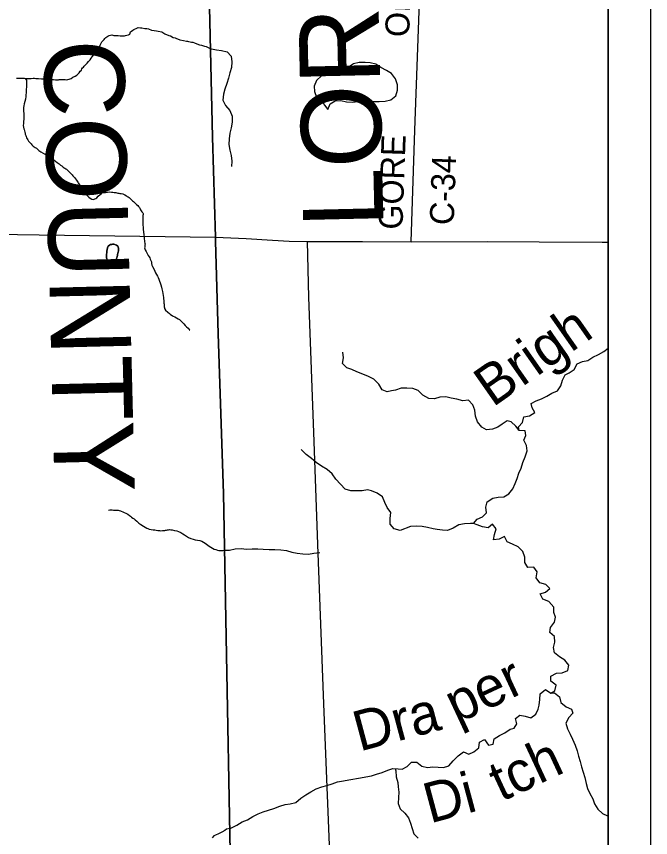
# Model space of a CAD drawing. Extents: x 0 to 34, y 0 to 22.
# Drawn here: x 7.504 to 9, y 15.642 to 17.578 of the extents above; entities that cross this region are included whole.
import ezdxf

# ---------------------------------------------------------------- set-up
doc = ezdxf.new("R2010")
doc.units = 0
for name, color, linetype in [('GM_X_Corporation', 7, 'Continuous'), ('GM_X_County_Road', 7, 'Continuous'), ('GM_X_County_Road_Text', 7, 'Continuous'), ('GM_X_County_Text', 7, 'Continuous'), ('GM_X_Minor_Lake', 7, 'Continuous'), ('GM_X_Minor_River', 7, 'Continuous'), ('GM_X_Minor_River_Text', 7, 'Continuous'), ('GM_X_State_Route', 7, 'Continuous'), ('SH_Data', 7, 'Continuous')]:
    doc.layers.add(name, color=color, linetype=linetype)

msp = doc.modelspace()

# ---------------------------------------------------------------- linework, layer by layer
at = {"layer": 'GM_X_Corporation'}
for points in [[(8.9, 14.1), (8.9, 20.9)], [(8.0153, 15.2273), (7.992, 16.4534), (7.9799, 16.8298), (7.9733, 17.0489), (7.973, 17.0583), (7.9659, 17.2939), (7.9575, 17.6697), (7.951, 17.9078), (7.9387, 18.4008), (7.9196, 19.2769), (6.5603, 19.2769), (6.5603, 19.994)], [(8.0153, 15.2273), (7.992, 16.4534), (7.9799, 16.8298), (7.9733, 17.0489), (7.973, 17.0583), (7.9659, 17.2939), (7.9575, 17.6697), (7.951, 17.9078), (7.9387, 18.4008), (7.9196, 19.2769), (6.5603, 19.2769), (6.5603, 19.994)], [(8.7801, 19.994), (8.7801, 19.2769), (7.9196, 19.2769), (7.9387, 18.4008), (7.951, 17.9078), (7.9575, 17.6697), (7.9659, 17.2939), (7.973, 17.0583), (7.9733, 17.0489), (7.9799, 16.8298), (7.992, 16.4534), (8.0153, 15.2273)]]:
    msp.add_lwpolyline(points, dxfattribs=at)
msp.add_lwpolyline([(7.9196, 19.2769), (7.9387, 18.4008), (7.951, 17.9078), (7.9575, 17.6697), (7.9659, 17.2939), (7.973, 17.0583), (7.9733, 17.0489), (7.9799, 16.8298), (7.992, 16.4534), (8.0153, 15.2273), (8.0262, 14.6555), (8.0297, 14.4963), (8.2922, 14.4944), (8.9, 14.4898), (8.9, 19.6997), (8.7801, 19.7002), (8.7801, 19.2769)], close=True, dxfattribs=at)
at = {"layer": 'GM_X_County_Road'}
for points in [[(8.435, 17.0471), (8.4437, 17.3104), (8.465, 17.8934), (8.4882, 18.5028)], [(8.2463, 15.5263), (8.2291, 15.9577), (8.215, 16.333), (8.206, 16.5759), (8.1937, 16.9162), (8.1904, 17.0478)], [(8.1904, 17.0478), (8.3202, 17.0474), (8.435, 17.0471)]]:
    msp.add_lwpolyline(points, dxfattribs=at)
at = {"layer": 'GM_X_Minor_Lake'}
for points in [[(8.3638, 17.4584), (8.3514, 17.4662), (8.3385, 17.4694), (8.3263, 17.47), (8.3126, 17.4698), (8.2988, 17.467), (8.2873, 17.4592), (8.2736, 17.4556), (8.261, 17.4569), (8.2484, 17.4533), (8.2346, 17.447), (8.2231, 17.4385), (8.2119, 17.4272), (8.2064, 17.4144), (8.2066, 17.4011), (8.2117, 17.3881), (8.2242, 17.3803), (8.2309, 17.3695), (8.2387, 17.3587)], [(8.2387, 17.3587), (8.2439, 17.3727), (8.2561, 17.3798), (8.2687, 17.38), (8.2824, 17.3771), (8.2961, 17.3765), (8.3098, 17.3778), (8.3235, 17.3795), (8.3372, 17.3785), (8.3467, 17.3776), (8.3597, 17.3782), (8.3738, 17.3784), (8.3868, 17.3816), (8.3991, 17.3909), (8.4027, 17.4045), (8.4029, 17.4175), (8.3981, 17.4312), (8.3884, 17.4436), (8.3767, 17.4513), (8.3638, 17.4584)], [(7.7194, 17.035), (7.7178, 17.0299), (7.7174, 17.028), (7.717, 17.0261), (7.7166, 17.0242), (7.7166, 17.0211), (7.7162, 17.0181), (7.7161, 17.0116), (7.7165, 17.0093), (7.7169, 17.0067), (7.7184, 17.0036), (7.721, 17.0013), (7.7229, 17.0002), (7.7264, 16.9994), (7.7325, 16.9993), (7.7359, 17.0012), (7.7374, 17.0031), (7.7386, 17.005), (7.7397, 17.0073), (7.7405, 17.0092), (7.7417, 17.0122), (7.7421, 17.0149), (7.7424, 17.0168), (7.7432, 17.0202), (7.744, 17.0225), (7.7444, 17.0255), (7.7448, 17.0289), (7.7448, 17.0323), (7.7426, 17.0365), (7.7399, 17.0388), (7.7376, 17.0396), (7.7357, 17.0404), (7.7331, 17.0412), (7.7304, 17.0412), (7.7285, 17.0408), (7.7258, 17.0405), (7.7235, 17.0393)], [(7.7235, 17.0393), (7.7258, 17.0405), (7.7285, 17.0408), (7.7304, 17.0412), (7.7331, 17.0412), (7.7357, 17.0404), (7.7376, 17.0396), (7.7399, 17.0388), (7.7426, 17.0365), (7.7448, 17.0323), (7.7448, 17.0289), (7.7444, 17.0255), (7.744, 17.0225), (7.7432, 17.0202), (7.7424, 17.0168), (7.7421, 17.0149), (7.7417, 17.0122), (7.7405, 17.0092), (7.7397, 17.0073), (7.7386, 17.005), (7.7374, 17.0031), (7.7359, 17.0012), (7.7325, 16.9993), (7.7264, 16.9994), (7.7229, 17.0002), (7.721, 17.0013), (7.7184, 17.0036), (7.7169, 17.0067), (7.7165, 17.0093), (7.7161, 17.0116), (7.7162, 17.0181), (7.7166, 17.0211), (7.7166, 17.0242), (7.717, 17.0261), (7.7174, 17.028), (7.7178, 17.0299), (7.7194, 17.035)], [(7.7235, 17.0393), (7.7201, 17.0371), (7.7194, 17.035)], [(7.7194, 17.035), (7.7201, 17.0371), (7.7235, 17.0393)]]:
    msp.add_lwpolyline(points, dxfattribs=at)
at = {"layer": 'GM_X_Minor_River'}
for points in [[(7.6675, 17.4653), (7.6702, 17.468), (7.6736, 17.4721), (7.6774, 17.4763), (7.6801, 17.4797), (7.6824, 17.4835), (7.6851, 17.4869), (7.687, 17.4895), (7.6889, 17.4918), (7.6912, 17.4945), (7.6932, 17.4963), (7.6951, 17.4979), (7.6955, 17.4998), (7.6966, 17.5016), (7.6974, 17.5039), (7.6993, 17.5066), (7.7012, 17.5107), (7.7055, 17.5187), (7.7074, 17.521), (7.7104, 17.5244), (7.7124, 17.5266), (7.7147, 17.5289), (7.7166, 17.5304), (7.7193, 17.5319), (7.7223, 17.5334), (7.7257, 17.5345), (7.7284, 17.5353), (7.7337, 17.5337), (7.7368, 17.5337), (7.7414, 17.5333), (7.744, 17.5337), (7.7486, 17.5329), (7.7505, 17.5325), (7.7524, 17.5325), (7.7558, 17.5324), (7.7589, 17.5328), (7.7612, 17.5332), (7.7642, 17.5343), (7.7684, 17.5354), (7.7715, 17.5365), (7.773, 17.5418), (7.778, 17.5464), (7.781, 17.5479), (7.7879, 17.5509), (7.7906, 17.552), (7.7963, 17.5512), (7.7994, 17.5512), (7.8066, 17.55), (7.8115, 17.5499), (7.815, 17.5495), (7.8226, 17.5461), (7.8287, 17.5453), (7.834, 17.5445), (7.8382, 17.5437), (7.8465, 17.5421), (7.8541, 17.5371), (7.8629, 17.5336), (7.8671, 17.5328), (7.8731, 17.529), (7.8781, 17.5278), (7.88, 17.5274), (7.8895, 17.5235), (7.8982, 17.5216), (7.9047, 17.5204), (7.907, 17.5204), (7.91, 17.5192), (7.9138, 17.5184), (7.9169, 17.518), (7.9196, 17.5176), (7.9237, 17.5161), (7.9294, 17.5138), (7.9355, 17.5118), (7.9401, 17.5107), (7.9428, 17.5099), (7.945, 17.5091), (7.9473, 17.5087), (7.9511, 17.5072), (7.9622, 17.5023)], [(7.9622, 17.5023), (7.9639, 17.5021), (7.9757, 17.4996), (7.9878, 17.4983), (8.0007, 17.4947), (8.0105, 17.4847), (8.0122, 17.4717), (8.0109, 17.458), (8.0069, 17.4452), (8.0041, 17.4327), (8.0001, 17.4205), (7.9957, 17.4069), (7.9925, 17.3948), (7.9908, 17.3811), (7.9971, 17.3685), (8.0072, 17.3569), (8.0123, 17.3432), (8.0125, 17.3295), (8.0101, 17.3158), (8.0068, 17.3029), (8.0055, 17.29), (8.005, 17.2767), (8.0074, 17.263), (8.0107, 17.2504), (8.0116, 17.2375), (8.0111, 17.2242)], [(7.5035, 17.4326), (7.5077, 17.4326), (7.5111, 17.4325), (7.5145, 17.4329), (7.5195, 17.4329), (7.5222, 17.4325), (7.5244, 17.4324), (7.5279, 17.4324), (7.5298, 17.4324), (7.5385, 17.4323), (7.5435, 17.4331), (7.5465, 17.4331), (7.5496, 17.4323), (7.5557, 17.4319), (7.5629, 17.4314), (7.569, 17.431), (7.5732, 17.4306), (7.5759, 17.4302), (7.5785, 17.4302), (7.5827, 17.4305), (7.585, 17.4305), (7.5888, 17.4297), (7.5911, 17.4297), (7.596, 17.4289), (7.5999, 17.4293), (7.6029, 17.4292), (7.6048, 17.4296), (7.6082, 17.4296), (7.6128, 17.4299), (7.6162, 17.4299), (7.6189, 17.4295), (7.6227, 17.4291), (7.6307, 17.4317), (7.6326, 17.4321), (7.6365, 17.4351), (7.6422, 17.4377), (7.646, 17.4396), (7.6487, 17.4423), (7.6514, 17.4457), (7.6544, 17.4494), (7.6571, 17.4521), (7.6583, 17.4547), (7.6598, 17.457), (7.6617, 17.4589), (7.6633, 17.4608), (7.6652, 17.4631), (7.6675, 17.4653)], [(7.5244, 17.4324), (7.5275, 17.4279), (7.5271, 17.4282), (7.5275, 17.4256), (7.5271, 17.4225), (7.5274, 17.4203), (7.5274, 17.4176), (7.527, 17.4142), (7.527, 17.4111), (7.5266, 17.4081), (7.5266, 17.4047), (7.5266, 17.3997), (7.5266, 17.3974), (7.5262, 17.394), (7.5257, 17.3898), (7.525, 17.3834), (7.5238, 17.3781), (7.5222, 17.3724), (7.5211, 17.3674), (7.5203, 17.3636), (7.5203, 17.3613), (7.5202, 17.3583), (7.5206, 17.356), (7.521, 17.3488), (7.5209, 17.3457), (7.5213, 17.3408), (7.5209, 17.3359), (7.5201, 17.3305), (7.5201, 17.326), (7.5197, 17.321), (7.5204, 17.3176), (7.5212, 17.3138), (7.5219, 17.3115), (7.5227, 17.3088), (7.5234, 17.3058), (7.5242, 17.3039), (7.5245, 17.3012), (7.5253, 17.2993), (7.526, 17.2974), (7.5264, 17.2955), (7.5275, 17.2925), (7.5287, 17.2898), (7.5302, 17.2871), (7.5321, 17.2844), (7.5343, 17.2818), (7.5366, 17.2798), (7.5381, 17.2779), (7.54, 17.276), (7.543, 17.2729), (7.5457, 17.271), (7.548, 17.2691), (7.5506, 17.2676), (7.5533, 17.2653), (7.5567, 17.2626), (7.5609, 17.2595), (7.5666, 17.2561), (7.5723, 17.2526), (7.5776, 17.2495), (7.5829, 17.2464), (7.5867, 17.2437), (7.5916, 17.2407), (7.5958, 17.2372), (7.6, 17.2341), (7.6041, 17.2307), (7.6079, 17.228), (7.6106, 17.2265), (7.6125, 17.2249), (7.614, 17.223), (7.6163, 17.2215), (7.6182, 17.2203), (7.6201, 17.2192), (7.622, 17.218), (7.6299, 17.2104), (7.6322, 17.2077), (7.6352, 17.2046), (7.6371, 17.2027), (7.639, 17.2), (7.6413, 17.1977), (7.6428, 17.1958), (7.6455, 17.192), (7.647, 17.1901), (7.6485, 17.1878), (7.6496, 17.1859), (7.6511, 17.1836), (7.6523, 17.1813), (7.6545, 17.1782), (7.656, 17.1756), (7.6579, 17.1733), (7.6602, 17.171), (7.6629, 17.1668), (7.6648, 17.1645), (7.6674, 17.1614), (7.6693, 17.1584), (7.6708, 17.1561), (7.6727, 17.1538), (7.6742, 17.1519), (7.6776, 17.1496), (7.6814, 17.1476), (7.6845, 17.1469), (7.691, 17.1491), (7.6936, 17.151)], [(7.6936, 17.151), (7.6967, 17.1548), (7.7009, 17.1589), (7.7044, 17.1612), (7.7063, 17.1623), (7.7139, 17.1634), (7.7188, 17.1637), (7.723, 17.1645), (7.7276, 17.1641), (7.731, 17.164), (7.7345, 17.1636), (7.7379, 17.1629), (7.7409, 17.1625), (7.7432, 17.1621), (7.7451, 17.1617), (7.7478, 17.1613), (7.7508, 17.1609), (7.7546, 17.1601), (7.7577, 17.1585), (7.7596, 17.1578), (7.7634, 17.1555), (7.7649, 17.1535), (7.7672, 17.1528), (7.7694, 17.1512), (7.7732, 17.1478), (7.7755, 17.1459), (7.7778, 17.1439), (7.7797, 17.1424), (7.7823, 17.1394), (7.7846, 17.1374), (7.7869, 17.1351), (7.7903, 17.1325), (7.7914, 17.1305), (7.7941, 17.1279), (7.7945, 17.126), (7.796, 17.1221), (7.7994, 17.1176), (7.802, 17.1153), (7.8024, 17.1134), (7.8024, 17.1111), (7.802, 17.1088), (7.8016, 17.105), (7.8016, 17.1008), (7.8015, 17.0951), (7.8019, 17.0909), (7.8022, 17.0863), (7.8026, 17.0818), (7.803, 17.0765), (7.8037, 17.07), (7.804, 17.0639), (7.8048, 17.0582), (7.8051, 17.0536), (7.8059, 17.0498), (7.8062, 17.0471), (7.8066, 17.0441), (7.807, 17.0418), (7.8066, 17.0399), (7.8066, 17.038), (7.8065, 17.0354), (7.8062, 17.0331), (7.8069, 17.0308), (7.8076, 17.0277), (7.8095, 17.0243), (7.811, 17.0212), (7.8129, 17.0182), (7.8148, 17.0144), (7.8171, 17.0117), (7.8186, 17.009), (7.8193, 17.0064), (7.8209, 17.0029), (7.822, 16.9995), (7.8227, 16.9961), (7.8235, 16.9923), (7.8246, 16.9888), (7.8284, 16.9816), (7.8302, 16.9774), (7.8321, 16.9739), (7.834, 16.9701), (7.8363, 16.9663), (7.8378, 16.9625), (7.8397, 16.9587), (7.8415, 16.9545), (7.8431, 16.9503), (7.8442, 16.9453), (7.8457, 16.9404), (7.8468, 16.9358), (7.8479, 16.9297), (7.849, 16.9248), (7.8497, 16.9202), (7.8505, 16.9156), (7.8508, 16.9122), (7.8512, 16.9088), (7.8516, 16.9057), (7.8516, 16.9023), (7.8519, 16.8996), (7.8519, 16.8962), (7.8523, 16.8936), (7.853, 16.8913), (7.853, 16.8894), (7.8557, 16.8855), (7.8606, 16.8813)], [(7.8606, 16.8813), (7.8648, 16.8782), (7.8674, 16.8756), (7.8708, 16.8736), (7.8735, 16.8717), (7.8773, 16.8698), (7.8815, 16.8679), (7.8849, 16.8656), (7.8887, 16.8636), (7.8913, 16.861), (7.8948, 16.8575), (7.8985, 16.8533), (7.902, 16.8499), (7.905, 16.8468), (7.9088, 16.843), (7.911, 16.8403), (7.9126, 16.8384), (7.9122, 16.8384), (7.9126, 16.8384)], [(8.69, 16.6024), (8.6883, 16.6108), (8.6975, 16.6213), (8.7011, 16.6345), (8.7141, 16.637), (8.7268, 16.6444), (8.7209, 16.6552), (8.718, 16.6658), (8.7302, 16.6721), (8.7425, 16.6765), (8.7551, 16.6828), (8.767, 16.6898), (8.78, 16.6957), (8.7886, 16.7074), (8.7922, 16.721), (8.7981, 16.7331), (8.8077, 16.7379), (8.8196, 16.7461), (8.827, 16.7593), (8.8392, 16.7644), (8.8518, 16.7669), (8.8638, 16.7747), (8.8772, 16.7809), (8.8898, 16.788), (8.9, 16.7963)], [(8.69, 16.6024), (8.6822, 16.6124), (8.6709, 16.6224), (8.6614, 16.6245), (8.6499, 16.6167), (8.6395, 16.6096), (8.6269, 16.6052), (8.6132, 16.6039), (8.6018, 16.6102), (8.5917, 16.6221), (8.5869, 16.6359), (8.5856, 16.6496), (8.5805, 16.6622), (8.5703, 16.6738), (8.5566, 16.6721), (8.543, 16.6761), (8.5293, 16.6786), (8.5168, 16.6814), (8.5027, 16.6809), (8.4901, 16.6769), (8.4764, 16.6775), (8.4624, 16.6857), (8.4519, 16.6961), (8.4386, 16.7009), (8.4249, 16.7022), (8.4112, 16.7021), (8.3982, 16.6969), (8.3887, 16.6959), (8.3787, 16.6934), (8.367, 16.6982), (8.3588, 16.7112), (8.3472, 16.7228), (8.3347, 16.7295), (8.3207, 16.735), (8.307, 16.7405), (8.2949, 16.7457), (8.2832, 16.7496), (8.273, 16.7597), (8.2751, 16.7733), (8.2742, 16.7867)], [(8.5906, 16.3792), (8.5819, 16.3831), (8.5904, 16.3932), (8.6031, 16.3984), (8.6127, 16.4077), (8.611, 16.4214), (8.6146, 16.4339), (8.6277, 16.4421), (8.6403, 16.4446), (8.654, 16.4459), (8.6655, 16.4525), (8.6748, 16.4646), (8.6807, 16.4774), (8.6854, 16.4887), (8.6894, 16.5012), (8.6949, 16.5133), (8.6989, 16.5262), (8.704, 16.5402), (8.7088, 16.5538), (8.7071, 16.5664), (8.7008, 16.579), (8.7059, 16.59), (8.7037, 16.6014), (8.69, 16.6024)], [(8.5819, 16.3831), (8.5747, 16.3824), (8.561, 16.3823), (8.5472, 16.3794), (8.5342, 16.3716), (8.5211, 16.3661), (8.509, 16.3671), (8.4961, 16.3688), (8.4866, 16.3705), (8.4737, 16.3733), (8.4607, 16.3758), (8.447, 16.3764), (8.4333, 16.3758), (8.4088, 16.3663), (8.3952, 16.3699), (8.3858, 16.3815), (8.3852, 16.3948), (8.387, 16.4085), (8.3784, 16.4204), (8.3728, 16.4326), (8.3673, 16.4457), (8.3552, 16.4542), (8.3416, 16.4597), (8.3321, 16.4618), (8.3191, 16.4601), (8.3062, 16.4599), (8.2925, 16.4601), (8.2792, 16.4634), (8.268, 16.4757), (8.2575, 16.4876), (8.2489, 16.4999), (8.2365, 16.51), (8.2232, 16.5178), (8.2112, 16.5267), (8.1995, 16.5357), (8.1875, 16.5457), (8.1758, 16.5573)], [(7.7206, 16.4144), (7.7241, 16.4148), (7.7275, 16.4151), (7.7298, 16.4148), (7.7328, 16.4144), (7.7366, 16.4143), (7.7404, 16.4143), (7.7435, 16.4143), (7.7458, 16.4135), (7.7492, 16.4123), (7.7632, 16.4065), (7.7667, 16.4046), (7.7701, 16.4019), (7.7727, 16.4), (7.7754, 16.3977), (7.7784, 16.3954), (7.7811, 16.3935), (7.7841, 16.3912), (7.7875, 16.3881), (7.7921, 16.3835), (7.7974, 16.3804), (7.8035, 16.3766), (7.8073, 16.3739), (7.8111, 16.372), (7.8137, 16.3708), (7.8171, 16.3697), (7.8217, 16.3685), (7.8263, 16.3681), (7.8301, 16.3677), (7.8335, 16.3673), (7.8373, 16.3665), (7.8411, 16.3661), (7.8438, 16.3657), (7.848, 16.366), (7.851, 16.366), (7.8537, 16.3664), (7.8556, 16.3667), (7.8579, 16.3671), (7.8598, 16.3675), (7.8628, 16.3678), (7.8651, 16.3682), (7.8678, 16.3678), (7.8712, 16.3678), (7.8769, 16.3666), (7.8819, 16.3654), (7.8864, 16.3635), (7.8914, 16.3612), (7.8959, 16.3585), (7.9001, 16.3558), (7.9047, 16.3531), (7.9096, 16.35), (7.9153, 16.3473), (7.9206, 16.3458), (7.9256, 16.3446), (7.9305, 16.3434), (7.9366, 16.3426), (7.9408, 16.3411), (7.945, 16.3391), (7.9488, 16.3364), (7.9586, 16.3295), (7.9624, 16.3272), (7.9666, 16.3249), (7.9704, 16.3226), (7.9742, 16.3214), (7.978, 16.3199), (7.9811, 16.3191), (7.9833, 16.3187), (7.9856, 16.3187), (7.9879, 16.3187), (7.9906, 16.319), (7.9955, 16.3197)], [(8.7644, 15.9829), (8.7744, 15.9885), (8.7773, 16.0014), (8.7648, 16.0107), (8.7646, 16.0229), (8.7777, 16.0299), (8.7914, 16.0308), (8.8048, 16.0359), (8.8072, 16.0488), (8.7979, 16.0604), (8.785, 16.0686), (8.773, 16.0779), (8.7709, 16.0905), (8.7741, 16.103), (8.7735, 16.1163), (8.7622, 16.1256), (8.7639, 16.1377), (8.7732, 16.1501), (8.7753, 16.1619), (8.7716, 16.173), (8.7714, 16.1855), (8.7598, 16.1986), (8.7458, 16.2045), (8.7391, 16.2172), (8.7518, 16.2212), (8.7625, 16.2294), (8.7528, 16.2387), (8.7387, 16.2431), (8.7301, 16.255), (8.7322, 16.2686), (8.7244, 16.2794), (8.7107, 16.2788), (8.7036, 16.2907), (8.7034, 16.3037), (8.6986, 16.3167), (8.6874, 16.3279), (8.6745, 16.3341), (8.6616, 16.3397), (8.6554, 16.3523), (8.6427, 16.346), (8.6293, 16.344), (8.6318, 16.3569), (8.6354, 16.3705), (8.6272, 16.3809), (8.6168, 16.3727), (8.6031, 16.3748), (8.5906, 16.3792)], [(7.9955, 16.3197), (8.0061, 16.3196), (8.0199, 16.3232), (8.0336, 16.3241), (8.0465, 16.3224), (8.0595, 16.3229), (8.0732, 16.3231), (8.0861, 16.3222), (8.0998, 16.3216), (8.1135, 16.3217), (8.1272, 16.3208), (8.1409, 16.319), (8.1534, 16.3154), (8.1663, 16.3126), (8.1793, 16.3112), (8.193, 16.3106), (8.2055, 16.3127), (8.2193, 16.3144)], [(8.008, 15.6633), (8.0234, 15.6713), (8.0361, 15.6791), (8.0487, 15.6843), (8.0618, 15.6917), (8.074, 15.6979), (8.0859, 15.7031), (8.0981, 15.7067), (8.1111, 15.7103), (8.1249, 15.7162), (8.1376, 15.7202), (8.1498, 15.7215), (8.1627, 15.7247), (8.1747, 15.7348), (8.1866, 15.743), (8.1985, 15.7501), (8.2112, 15.7567), (8.2242, 15.7615), (8.236, 15.7647), (8.2486, 15.7687), (8.2616, 15.7738), (8.275, 15.7763), (8.288, 15.778), (8.3155, 15.7829), (8.3284, 15.785), (8.3414, 15.7878), (8.3536, 15.7914), (8.3663, 15.7954), (8.38, 15.8009), (8.3919, 15.8049), (8.4041, 15.8044), (8.4136, 15.8035), (8.4259, 15.8097), (8.4355, 15.8202), (8.4481, 15.8197), (8.4605, 15.8107), (8.4734, 15.8075), (8.486, 15.8092), (8.4989, 15.8082), (8.5115, 15.8073), (8.5241, 15.8109), (8.5345, 15.8229), (8.5457, 15.8345), (8.5588, 15.8446), (8.5713, 15.8391), (8.5828, 15.8446), (8.5951, 15.8536), (8.5965, 15.8672), (8.608, 15.8731), (8.6177, 15.8601), (8.6288, 15.8626), (8.6308, 15.8751), (8.6435, 15.8829), (8.6562, 15.8891), (8.6685, 15.8977), (8.6784, 15.8998), (8.6842, 15.91), (8.681, 15.923), (8.6918, 15.9304), (8.7043, 15.9283), (8.7176, 15.9247), (8.7291, 15.9329), (8.735, 15.945), (8.737, 15.9545), (8.7387, 15.9674), (8.7397, 15.981), (8.7524, 15.9911), (8.7644, 15.9829)], [(8.7644, 15.9829), (8.7732, 15.9836), (8.7853, 15.9743), (8.7885, 15.9605), (8.8005, 15.9508), (8.813, 15.9453), (8.8163, 15.9358), (8.807, 15.9256), (8.8004, 15.912), (8.8036, 15.8987), (8.8103, 15.886), (8.8158, 15.8738), (8.8217, 15.86), (8.8269, 15.8466), (8.8298, 15.8344), (8.8338, 15.8214), (8.8367, 15.8092), (8.841, 15.7962), (8.8447, 15.7836), (8.8483, 15.7699), (8.8515, 15.7576), (8.8563, 15.7458), (8.8634, 15.7331), (8.8678, 15.7213), (8.8752, 15.709), (8.8869, 15.6986), (8.8986, 15.6934), (8.9, 15.693)], [(8.3973, 15.8047), (8.3987, 15.7991), (8.3996, 15.7854), (8.4032, 15.7717), (8.4046, 15.7621), (8.4056, 15.7492), (8.4054, 15.7363), (8.4045, 15.7226), (8.4092, 15.71), (8.4198, 15.6999), (8.4291, 15.6884), (8.4335, 15.6761), (8.4375, 15.6632), (8.4412, 15.6509), (8.4517, 15.6409)], [(8.008, 15.6633), (7.9993, 15.6617), (7.9951, 15.6591), (7.9882, 15.655), (7.9806, 15.6508), (7.9737, 15.6478), (7.9695, 15.646), (7.9653, 15.6418)]]:
    msp.add_lwpolyline(points, dxfattribs=at)
at = {"layer": 'GM_X_State_Route'}
for points in [[(6.36, 17.1383), (6.363, 17.1377), (6.38, 17.1337), (6.4007, 17.1289), (6.4148, 17.1254), (6.4314, 17.1195), (6.4492, 17.1109), (6.4641, 17.1046), (6.4792, 17.0998), (6.4953, 17.0958), (6.5156, 17.0912), (6.5453, 17.0862), (6.5736, 17.0818), (6.6097, 17.0791), (6.8131, 17.0745), (6.9289, 17.0721), (7.1484, 17.0701), (7.557, 17.0633), (7.9732, 17.0578)], [(7.9732, 17.0578), (8.0455, 17.0547), (8.1077, 17.0507), (8.1474, 17.0488), (8.1904, 17.0478)], [(8.1904, 17.0478), (8.3202, 17.0474), (8.435, 17.0471)], [(8.435, 17.0471), (8.6148, 17.0478), (8.7368, 17.0471), (8.8854, 17.0464), (8.9, 17.0464)]]:
    msp.add_lwpolyline(points, dxfattribs=at)
at = {"layer": 'SH_Data'}
for p, q in [((9, 21), (9, 14)), ((8.9, 20.9), (8.9, 14.1))]:
    msp.add_line(p, q, dxfattribs=at)

# ---------------------------------------------------------------- texts
at = {"layer": 'GM_X_County_Road_Text'}
for s, rotation, p in [('ORPHANAGE', 88.0322, (8.4302, 17.5291)), ('GORE', 87.9817, (8.4144, 17.075)), ('C-34', 87.9422, (8.5354, 17.0857))]:
    msp.add_text(s, height=0.05682, rotation=rotation, dxfattribs=at).set_placement(p)
at = {"layer": 'GM_X_County_Text'}
for s, rotation, p in [('LORAIN COUNTY', 91.3059, (8.3699, 17.082)), ('HURON COUNTY', 271.4235, (7.5424, 18.5207))]:
    msp.add_text(s, height=0.189394, rotation=rotation, dxfattribs=at).set_placement(p)
at = {"layer": 'GM_X_Minor_River_Text'}
for s, height, rotation, p in [('Brigh', 0.09475, 34.9987, (8.6274, 16.6556)), ('per', 0.09475, 24.9985, (8.5426, 15.9097)), ('Dra', 0.09474, 14.9981, (8.3132, 15.8447)), ('tch', 0.09475, 24.9983, (8.6478, 15.7258)), ('Di', 0.09474, 14.9981, (8.4794, 15.6751))]:
    msp.add_text(s, height=height, rotation=rotation, dxfattribs=at).set_placement(p)

doc.saveas('drawing.dxf')
